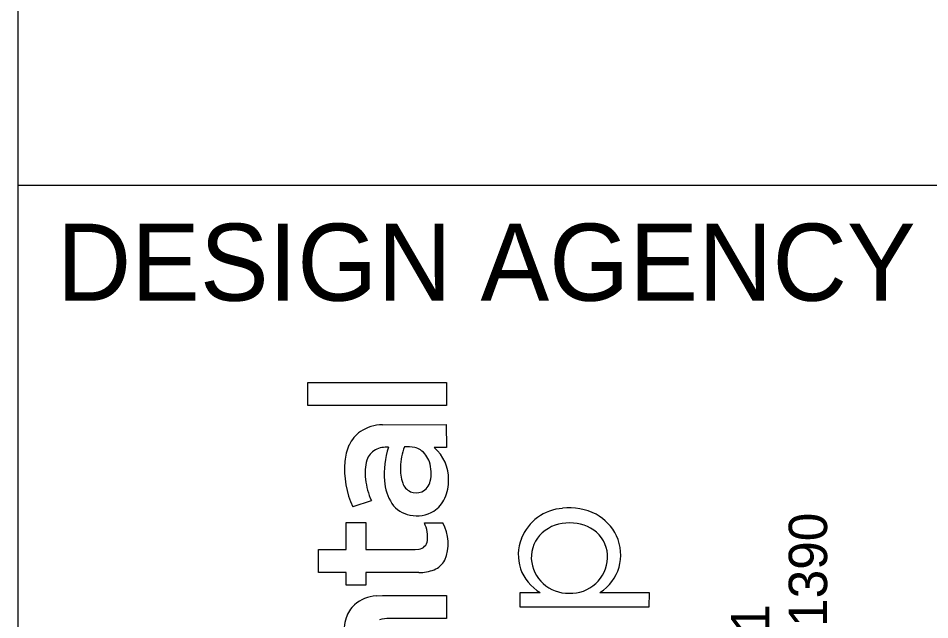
# Model space of a CAD drawing. Extents: x -4.2 to 34, y 0 to 22.
# Drawn here: x 32 to 33.183, y 4.436 to 5.217 of the extents above; entities that cross this region are included whole.
import ezdxf

# ---------------------------------------------------------------- set-up
doc = ezdxf.new("R2010")
doc.units = 0
doc.layers.add('SH_Border', color=7, linetype='Continuous')
doc.layers.add('SH_Data', color=7, linetype='Continuous')

msp = doc.modelspace()

# ---------------------------------------------------------------- linework, layer by layer
at = {"layer": 'SH_Border'}
for p, q in [((32, 0.5), (32, 21.5)), ((32, 5), (33.5, 5))]:
    msp.add_line(p, q, dxfattribs=at)
at = {"layer": 'SH_Data'}
for p, q in [((32.3756, 4.7141), (32.3756, 4.744)), ((32.3756, 4.744), (32.5557, 4.744)), ((32.5557, 4.744), (32.5557, 4.7141)), ((32.5557, 4.7141), (32.3756, 4.7141)), ((32.4727, 4.689), (32.5555, 4.6892)), ((32.5555, 4.6892), (32.5557, 4.6596)), ((32.5557, 4.6596), (32.5397, 4.6596)), ((32.4582, 4.5904), (32.4343, 4.5823)), ((32.4254, 4.527), (32.4255, 4.5621)), ((32.4255, 4.5621), (32.4511, 4.5621)), ((32.4511, 4.5621), (32.4512, 4.527)), ((32.527, 4.5616), (32.5511, 4.5616)), ((32.3896, 4.4972), (32.3896, 4.527)), ((32.3896, 4.527), (32.4254, 4.527)), ((32.4512, 4.527), (32.515, 4.527)), ((32.515, 4.527), (32.52, 4.5275)), ((32.4254, 4.4972), (32.3896, 4.4972)), ((32.4254, 4.4807), (32.4254, 4.4972)), ((32.5197, 4.4972), (32.4511, 4.4972)), ((32.4511, 4.4972), (32.4511, 4.4807)), ((32.4511, 4.4807), (32.4254, 4.4807)), ((32.7549, 4.4713), (32.8186, 4.4711)), ((32.4644, 4.4669), (32.4729, 4.4673)), ((32.4729, 4.4673), (32.5557, 4.4673)), ((32.5557, 4.4673), (32.5557, 4.4375)), ((32.6515, 4.4521), (32.6515, 4.4711)), ((32.6515, 4.4711), (32.6771, 4.4711)), ((32.8186, 4.4711), (32.8184, 4.4521)), ((32.8184, 4.4521), (32.6515, 4.4521)), ((32.5557, 4.4375), (32.4814, 4.4375))]:
    msp.add_line(p, q, dxfattribs=at)
msp.add_lwpolyline([(32.3756, 4.7141), (32.3756, 4.744), (32.5557, 4.744), (32.5557, 4.7141)], close=True, dxfattribs=at)
for points in [[(32.4727, 4.689), (32.5555, 4.6892), (32.5557, 4.6596)], [(32.5557, 4.6596), (32.5397, 4.6596)], [(32.4582, 4.5904), (32.4343, 4.5823)], [(32.5197, 4.4972), (32.4511, 4.4972), (32.4511, 4.4807), (32.4254, 4.4807), (32.4254, 4.4972), (32.3896, 4.4972), (32.3896, 4.527), (32.4254, 4.527), (32.4255, 4.5621), (32.4511, 4.5621), (32.4512, 4.527), (32.515, 4.527), (32.52, 4.5275)], [(32.527, 4.5616), (32.5511, 4.5616)], [(32.7549, 4.4713), (32.8186, 4.4711), (32.8184, 4.4521), (32.6515, 4.4521)], [(32.4644, 4.4669), (32.4729, 4.4673), (32.5557, 4.4673), (32.5557, 4.4375), (32.4814, 4.4375)], [(32.6515, 4.4521), (32.6515, 4.4711), (32.6771, 4.4711)]]:
    msp.add_lwpolyline(points, dxfattribs=at)
for centre, radius, start, end in [((32.4745, 4.6326), 0.0565, 91.8942, 122.6317), ((32.4745, 4.6326), 0.0565, 91.8942, 122.6317), ((32.4685, 4.6447), 0.043, 124.537, 155.6594), ((32.4685, 4.6447), 0.043, 124.537, 155.6594), ((32.4882, 4.6361), 0.0646, 155.9764, 175.3149), ((32.4882, 4.6361), 0.0646, 155.9764, 175.3149), ((32.4753, 4.6356), 0.024, 119.4252, 161.6629), ((32.4753, 4.6356), 0.024, 119.4252, 161.6629), ((32.4779, 4.6278), 0.0321, 85.3802, 116.6222), ((32.4779, 4.6278), 0.0321, 85.3802, 116.6222), ((32.5879, 4.6251), 0.1129, 162.0821, 184.5285), ((32.5879, 4.6251), 0.1129, 162.0821, 184.5285), ((32.5801, 4.6313), 0.0841, 159.8366, 178.0362), ((32.5801, 4.6313), 0.0841, 159.8366, 178.0362), ((32.5051, 4.6074), 0.053, 79.6696, 94.2322), ((32.5051, 4.6074), 0.053, 79.6696, 94.2322), ((32.5089, 4.6364), 0.0238, 56.8913, 76.2149), ((32.5089, 4.6364), 0.0238, 56.8913, 76.2149), ((32.5052, 4.6318), 0.0297, 17.5984, 55.7282), ((32.5052, 4.6318), 0.0297, 17.5984, 55.7282), ((32.5055, 4.6191), 0.0529, 358.0746, 49.762), ((32.5055, 4.6191), 0.0529, 358.0746, 49.762), ((32.5364, 4.6308), 0.113, 174.6101, 205.3899), ((32.5364, 4.6308), 0.113, 174.6101, 205.3899), ((32.5076, 4.6265), 0.0576, 163.1369, 188.1675), ((32.5076, 4.6265), 0.0576, 163.1369, 188.1675), ((32.4916, 4.6264), 0.0443, 345.9408, 18.9919), ((32.4916, 4.6264), 0.0443, 345.9408, 18.9919), ((32.5466, 4.6303), 0.0506, 175.5903, 199.8857), ((32.5466, 4.6303), 0.0506, 175.5903, 199.8857), ((32.5473, 4.6297), 0.0973, 186.7598, 203.7981), ((32.5473, 4.6297), 0.0973, 186.7598, 203.7981), ((32.5328, 4.6187), 0.0575, 182.5676, 213.7144), ((32.5328, 4.6187), 0.0575, 182.5676, 213.7144), ((32.5152, 4.6199), 0.0199, 295.2883, 347.4639), ((32.5152, 4.6199), 0.0199, 295.2883, 347.4639), ((32.5019, 4.6168), 0.0566, 336.016, 0.5951), ((32.5019, 4.6168), 0.0566, 336.016, 0.5951), ((32.5164, 4.6189), 0.0184, 198.2844, 293.3081), ((32.5164, 4.6189), 0.0184, 198.2844, 293.3081), ((32.5175, 4.6097), 0.0394, 303.4436, 336.18), ((32.5175, 4.6097), 0.0394, 303.4436, 336.18), ((32.5149, 4.6078), 0.0366, 215.0668, 259.8133), ((32.5149, 4.6078), 0.0366, 215.0668, 259.8133), ((32.7108, 4.5182), 0.0624, 93.9866, 158.3119), ((32.7108, 4.5182), 0.0624, 93.9866, 158.3119), ((32.7156, 4.5065), 0.0746, 62.6889, 97.0135), ((32.7156, 4.5065), 0.0746, 62.6889, 97.0135), ((32.5175, 4.6131), 0.0423, 257.5256, 300.882), ((32.5175, 4.6131), 0.0423, 257.5256, 300.882), ((32.7212, 4.5191), 0.0608, 25.0657, 61.9602), ((32.7212, 4.5191), 0.0608, 25.0657, 61.9602), ((32.4863, 4.542), 0.0452, 10.1545, 25.723), ((32.4863, 4.542), 0.0452, 10.1545, 25.723), ((32.503, 4.5351), 0.0549, 336.589, 28.8991), ((32.503, 4.5351), 0.0549, 336.589, 28.8991), ((32.7138, 4.5102), 0.0513, 87.8965, 131.1812), ((32.7138, 4.5102), 0.0513, 87.8965, 131.1812), ((32.7175, 4.5102), 0.0513, 49.9089, 92.0363), ((32.7175, 4.5102), 0.0513, 49.9089, 92.0363), ((32.4957, 4.5436), 0.0356, 351.914, 10.2059), ((32.4957, 4.5436), 0.0356, 351.914, 10.2059), ((32.7092, 4.5167), 0.0434, 132.3289, 182.0949), ((32.7092, 4.5167), 0.0434, 132.3289, 182.0949), ((32.7215, 4.5173), 0.0433, 358.0487, 47.9447), ((32.7215, 4.5173), 0.0433, 358.0487, 47.9447), ((32.7245, 4.52), 0.0574, 301.9776, 25.6418), ((32.7245, 4.52), 0.0574, 301.9776, 25.6418), ((32.5184, 4.54), 0.0126, 277.6142, 353.7918), ((32.5184, 4.54), 0.0126, 277.6142, 353.7918), ((32.707, 4.5202), 0.0581, 158.656, 198.171), ((32.707, 4.5202), 0.0581, 158.656, 198.171), ((32.5291, 4.5261), 0.0275, 292.6889, 332.0598), ((32.5291, 4.5261), 0.0275, 292.6889, 332.0598), ((32.7135, 4.5181), 0.0478, 183.5974, 271.7045), ((32.7135, 4.5181), 0.0478, 183.5974, 271.7045), ((32.7172, 4.518), 0.0477, 267.3149, 357.4019), ((32.7172, 4.518), 0.0477, 267.3149, 357.4019), ((32.5209, 4.5486), 0.0514, 268.6727, 291.5235), ((32.5209, 4.5486), 0.0514, 268.6727, 291.5235), ((32.7103, 4.5243), 0.0627, 200.8399, 238.0162), ((32.7103, 4.5243), 0.0627, 200.8399, 238.0162), ((32.4687, 4.4172), 0.0499, 94.9706, 130.2248), ((32.4687, 4.4172), 0.0499, 94.9706, 130.2248), ((32.4635, 4.4255), 0.0402, 132.2238, 161.6823), ((32.4635, 4.4255), 0.0402, 132.2238, 161.6823), ((32.4787, 4.4211), 0.056, 162.274, 187.7917), ((32.4787, 4.4211), 0.056, 162.274, 187.7917), ((32.4811, 4.3915), 0.046, 89.6051, 105.3303), ((32.4811, 4.3915), 0.046, 89.6051, 105.3303)]:
    msp.add_arc(centre, radius, start, end, dxfattribs=at)

# ---------------------------------------------------------------- texts
msp.add_text('DESIGN AGENCY', height=0.1, dxfattribs=at).set_placement((32.05, 4.85))
for s, p in [('800.835.1390', (33.0497, 4.1671)), ('450 GRANT ST., AKRON, OH  44311', (32.9749, 3.3374))]:
    msp.add_text(s, height=0.049846, rotation=90, dxfattribs=at).set_placement(p)

doc.saveas('drawing.dxf')
